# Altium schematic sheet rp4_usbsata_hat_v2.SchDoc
size A4
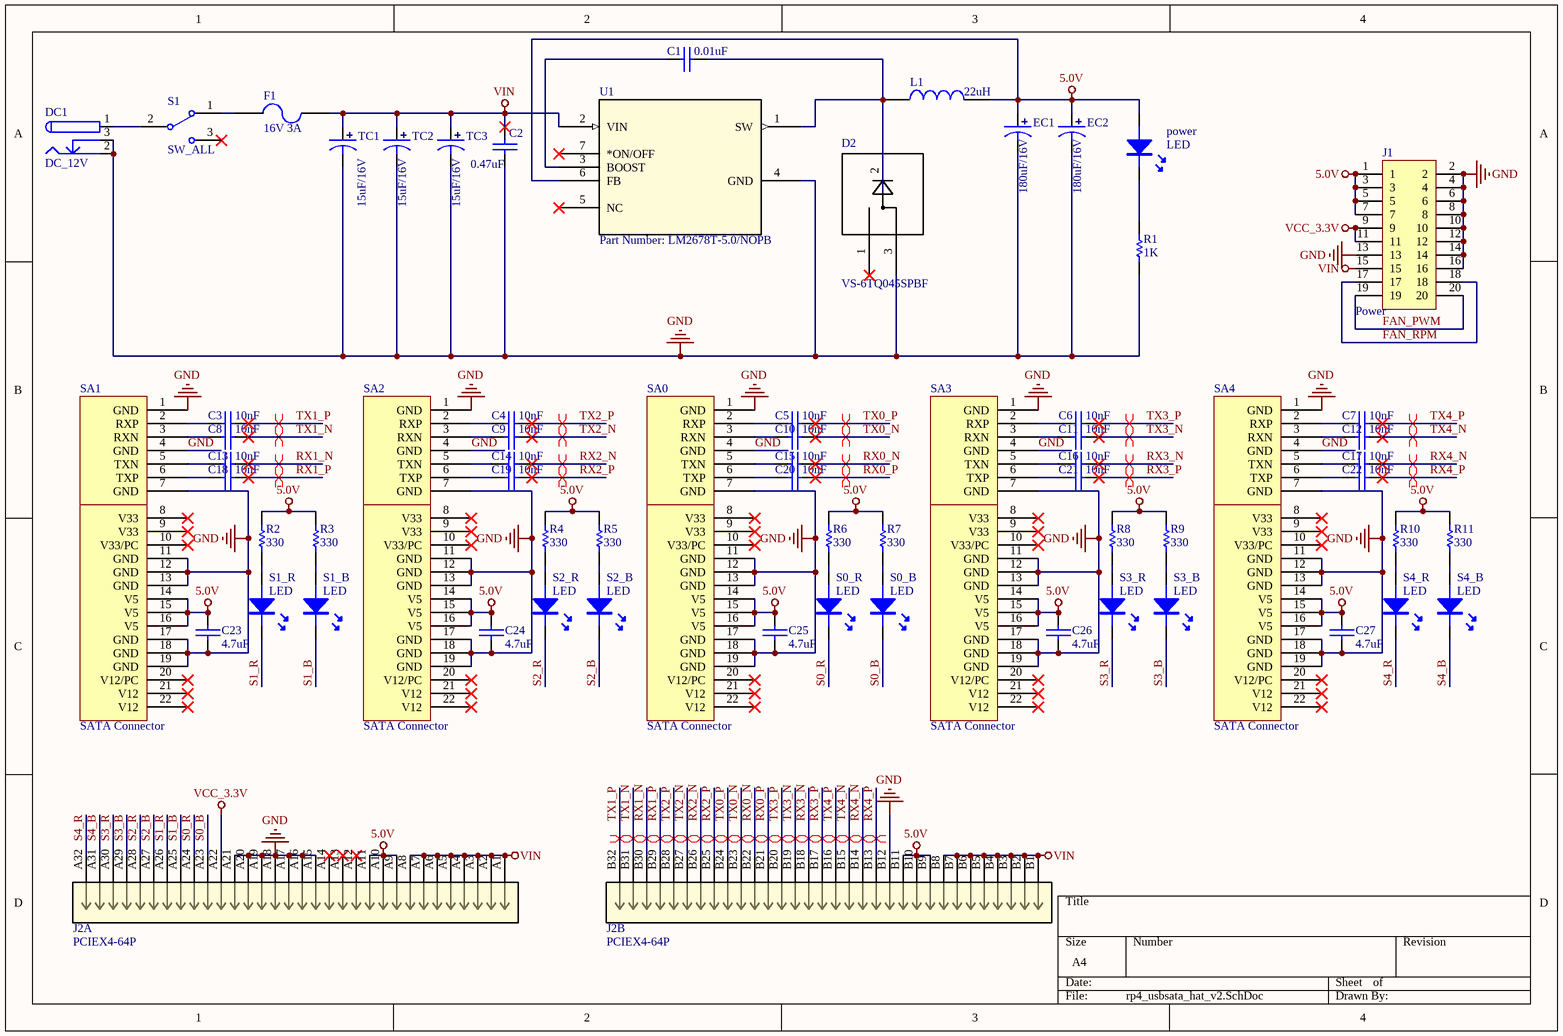
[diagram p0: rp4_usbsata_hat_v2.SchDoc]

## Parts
C1  0.01uF  [0603C]
C2  0.47uF  [0603C]
C3  10nF  [0603C]
C4  10nF  [0603C]
C5  10nF  [0603C]
C6  10nF  [0603C]
C7  10nF  [0603C]
C8  10nF  [0603C]
C9  10nF  [0603C]
C10  10nF  [0603C]
C11  10nF  [0603C]
C12  10nF  [0603C]
C13  10nF  [0603C]
C14  10nF  [0603C]
C15  10nF  [0603C]
C16  10nF  [0603C]
C17  10nF  [0603C]
C18  10nF  [0603C]
C19  10nF  [0603C]
C20  10nF  [0603C]
C21  10nF  [0603C]
C22  10nF  [0603C]
C23  4.7uF  [0603C]
C24  4.7uF  [0603C]
C25  4.7uF  [0603C]
C26  4.7uF  [0603C]
C27  4.7uF  [0603C]
D2  VS-6TQ045SPBF  [TO-263-2]
DC1  DC_12V  [DC-005]
EC1  180uF/16V  [SMD-EC6.3X6.3X10]
EC2  180uF/16V  [SMD-EC6.3X6.3X10]
F1  16V 3A  [FUSE-1812]
J1  Power  [Pin HDR2X10/2.54mm-S]
J2  PCIEX4-64P  [PCIEX4-64P]  (parts A,B of 2)
L1  22uH  [CDRH124]
power  LED  [LED-0603G]
R1  1K  [0603R]
R2  330  [0603R]
R3  330  [0603R]
R4  330  [0603R]
R5  330  [0603R]
R6  330  [0603R]
R7  330  [0603R]
R8  330  [0603R]
R9  330  [0603R]
R10  330  [0603R]
R11  330  [0603R]
S0_B  LED  [LED-0603W]
S0_R  LED  [LED-0603W]
S1  SW_ALL  [SS-12D10]
S1_B  LED  [LED-0603W]
S1_R  LED  [LED-0603W]
S2_B  LED  [LED-0603W]
S2_R  LED  [LED-0603W]
S3_B  LED  [LED-0603W]
S3_R  LED  [LED-0603W]
S4_B  LED  [LED-0603W]
S4_R  LED  [LED-0603W]
SA0  SATA Connector  [SATA Female]
SA1  SATA Connector  [SATA Female]
SA2  SATA Connector  [SATA Female]
SA3  SATA Connector  [SATA Female]
SA4  SATA Connector  [SATA Female]
TC1  15uF/16V  [TAJ-B/3528]
TC2  15uF/16V  [TAJ-B/3528]
TC3  15uF/16V  [TAJ-B/3528]
U1  Part Number: LM2678T-5.0/NOPB  [TA07Bm_TEX]

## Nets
5.0V: C23.1 C24.1 C25.1 C26.1 C27.1 EC1.1 EC2.1 J1.1 J1.3 J1.5 J1.7 J2.A9 J2.A10 J2.A11 J2.B9 J2.B10 J2.B11 L1.2 power.A R2.1 R3.1 R4.1 R5.1 R6.1 R7.1 R8.1 R9.1 R10.1 R11.1 SA0.14(V5) SA0.15(V5) SA0.16(V5) SA1.14(V5) SA1.15(V5) SA1.16(V5) SA2.14(V5) SA2.15(V5) SA2.16(V5) SA3.14(V5) SA3.15(V5) SA3.16(V5) SA4.14(V5) SA4.15(V5) SA4.16(V5) U1.6(FB)
GND: C2.1 C23.2 C24.2 C25.2 C26.2 C27.2 D2.3 DC1.2 DC1.3 EC1.2 EC2.2 J1.2 J1.4 J1.6 J1.8 J1.10 J1.12 J1.13 J1.14 J1.16 J2.A15 J2.A16 J2.A17 J2.A18 J2.A19 J2.A20 J2.A21 J2.B12 R1.1 SA0.1(GND) SA0.4(GND) SA0.7(GND) SA0.11(GND) SA0.12(GND) SA0.13(GND) SA0.17(GND) SA0.18(GND) SA0.19(GND) SA1.1(GND) SA1.4(GND) SA1.7(GND) SA1.11(GND) SA1.12(GND) SA1.13(GND) SA1.17(GND) SA1.18(GND) SA1.19(GND) SA2.1(GND) SA2.4(GND) SA2.7(GND) SA2.11(GND) SA2.12(GND) SA2.13(GND) SA2.17(GND) SA2.18(GND) SA2.19(GND) SA3.1(GND) SA3.4(GND) SA3.7(GND) SA3.11(GND) SA3.12(GND) SA3.13(GND) SA3.17(GND) SA3.18(GND) SA3.19(GND) SA4.1(GND) SA4.4(GND) SA4.7(GND) SA4.11(GND) SA4.12(GND) SA4.13(GND) SA4.17(GND) SA4.18(GND) SA4.19(GND) TC1.2 TC2.2 TC3.2 U1.4(GND)
VCC_3.3V: J1.9 J1.11 J2.A22
VIN: C2.2 F1.2 J1.15 J2.A1 J2.A2 J2.A3 J2.A4 J2.A5 J2.A6 J2.A7 J2.A8 J2.B1 J2.B2 J2.B3 J2.B4 J2.B5 J2.B6 J2.B7 J2.B8 TC1.1 TC2.1 TC3.1 U1.2(VIN)
FAN_PWM: J1.19 J1.20
FAN_RPM: J1.17 J1.18
RX0_N: C15.2 J2.B22
RX0_P: C20.2 J2.B21
RX1_N: C13.2 J2.B30
RX1_P: C18.2 J2.B29
RX2_N: C14.2 J2.B26
RX2_P: C19.2 J2.B25
RX3_N: C16.2 J2.B18
RX3_P: C21.2 J2.B17
RX4_N: C17.2 J2.B14
RX4_P: C22.2 J2.B13
S0_B: J2.A23 S0_B.K
S0_R: J2.A24 S0_R.K
S1_B: J2.A25 S1_B.K
S1_R: J2.A26 S1_R.K
S2_B: J2.A27 S2_B.K
S2_R: J2.A28 S2_R.K
S3_B: J2.A29 S3_B.K
S3_R: J2.A30 S3_R.K
S4_B: J2.A31 S4_B.K
S4_R: J2.A32 S4_R.K
TX0_N: C10.2 J2.B23
TX0_P: C5.2 J2.B24
TX1_N: C8.2 J2.B31
TX1_P: C3.2 J2.B32
TX2_N: C9.2 J2.B27
TX2_P: C4.2 J2.B28
TX3_N: C11.2 J2.B19
TX3_P: C6.2 J2.B20
TX4_N: C12.2 J2.B15
TX4_P: C7.2 J2.B16
NetC1_1: C1.1 U1.3(BOOST)
NetC1_2: C1.2 D2.2 L1.1 U1.1(SW)
NetC3_1: C3.1 SA1.2(RXP)
NetC4_1: C4.1 SA2.2(RXP)
NetC5_1: C5.1 SA0.2(RXP)
NetC6_1: C6.1 SA3.2(RXP)
NetC7_1: C7.1 SA4.2(RXP)
NetC8_1: C8.1 SA1.3(RXN)
NetC9_1: C9.1 SA2.3(RXN)
NetC10_1: C10.1 SA0.3(RXN)
NetC11_1: C11.1 SA3.3(RXN)
NetC12_1: C12.1 SA4.3(RXN)
NetC13_1: C13.1 SA1.5(TXN)
NetC14_1: C14.1 SA2.5(TXN)
NetC15_1: C15.1 SA0.5(TXN)
NetC16_1: C16.1 SA3.5(TXN)
NetC17_1: C17.1 SA4.5(TXN)
NetC18_1: C18.1 SA1.6(TXP)
NetC19_1: C19.1 SA2.6(TXP)
NetC20_1: C20.1 SA0.6(TXP)
NetC21_1: C21.1 SA3.6(TXP)
NetC22_1: C22.1 SA4.6(TXP)
NetDC1_1: DC1.1 S1.2
NetF1_1: F1.1 S1.1
Netpower_K: power.K R1.2
NetR2_2: R2.2 S1_R.A
NetR3_2: R3.2 S1_B.A
NetR4_2: R4.2 S2_R.A
NetR5_2: R5.2 S2_B.A
NetR6_2: R6.2 S0_R.A
NetR7_2: R7.2 S0_B.A
NetR8_2: R8.2 S3_R.A
NetR9_2: R9.2 S3_B.A
NetR10_2: R10.2 S4_R.A
NetR11_2: R11.2 S4_B.A

Not connected (* = marked no-connect by the designer): D2 1*; J2 A12* A13* A14*; S1 3*; SA0 8(V33)* 9(V33)* 10(V33/PC)* 20(V12/PC)* 21(V12)* 22(V12)*; SA1 8(V33)* 9(V33)* 10(V33/PC)* 20(V12/PC)* 21(V12)* 22(V12)*; SA2 8(V33)* 9(V33)* 10(V33/PC)* 20(V12/PC)* 21(V12)* 22(V12)*; SA3 8(V33)* 9(V33)* 10(V33/PC)* 20(V12/PC)* 21(V12)* 22(V12)*; SA4 8(V33)* 9(V33)* 10(V33/PC)* 20(V12/PC)* 21(V12)* 22(V12)*; U1 5(NC)* 7(*ON/OFF)*

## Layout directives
differential pair: RX0_N, RX0_P, RX1_N, RX1_P, RX2_N, RX2_P, RX3_N, RX3_P, RX4_N, RX4_P, TX0_N, TX0_P, TX1_N, TX1_P, TX2_N, TX2_P, TX3_N, TX3_P, TX4_N, TX4_P

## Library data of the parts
C1-C27 = CAP: 无极性电容
D2 = VS-6TQ045SPBF: 直流反向耐压（Vr）：45V 平均整流电流（Io）：6A 正向
DC1 = DC_Socket
EC1 EC2 = SMD_ECAP: 贴片电解电容
F1 = FUSE
J1 = Pin HDR2X10
J2 = PCIEX4-64P: No Description Available; Manufacturer_Part_Number: 87715-9106; Vendor: Molex Connector Corporation; Built_By: EMA_Cory; SourceLibrary: Molex_2020-01-22
L1 = INDUCTOR
R1-R11 = RES
S1 = SS-12D10
SA0-SA4 = SATA_Female_22P
TC1-TC3 = TCAP: 钽电容
U1 = LM2678T-5.0/NOPB: No Description Available; SourceLibrary: National_2011-09-26; Vendor: Texas Instruments; Built_By: EMA_UL_Team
